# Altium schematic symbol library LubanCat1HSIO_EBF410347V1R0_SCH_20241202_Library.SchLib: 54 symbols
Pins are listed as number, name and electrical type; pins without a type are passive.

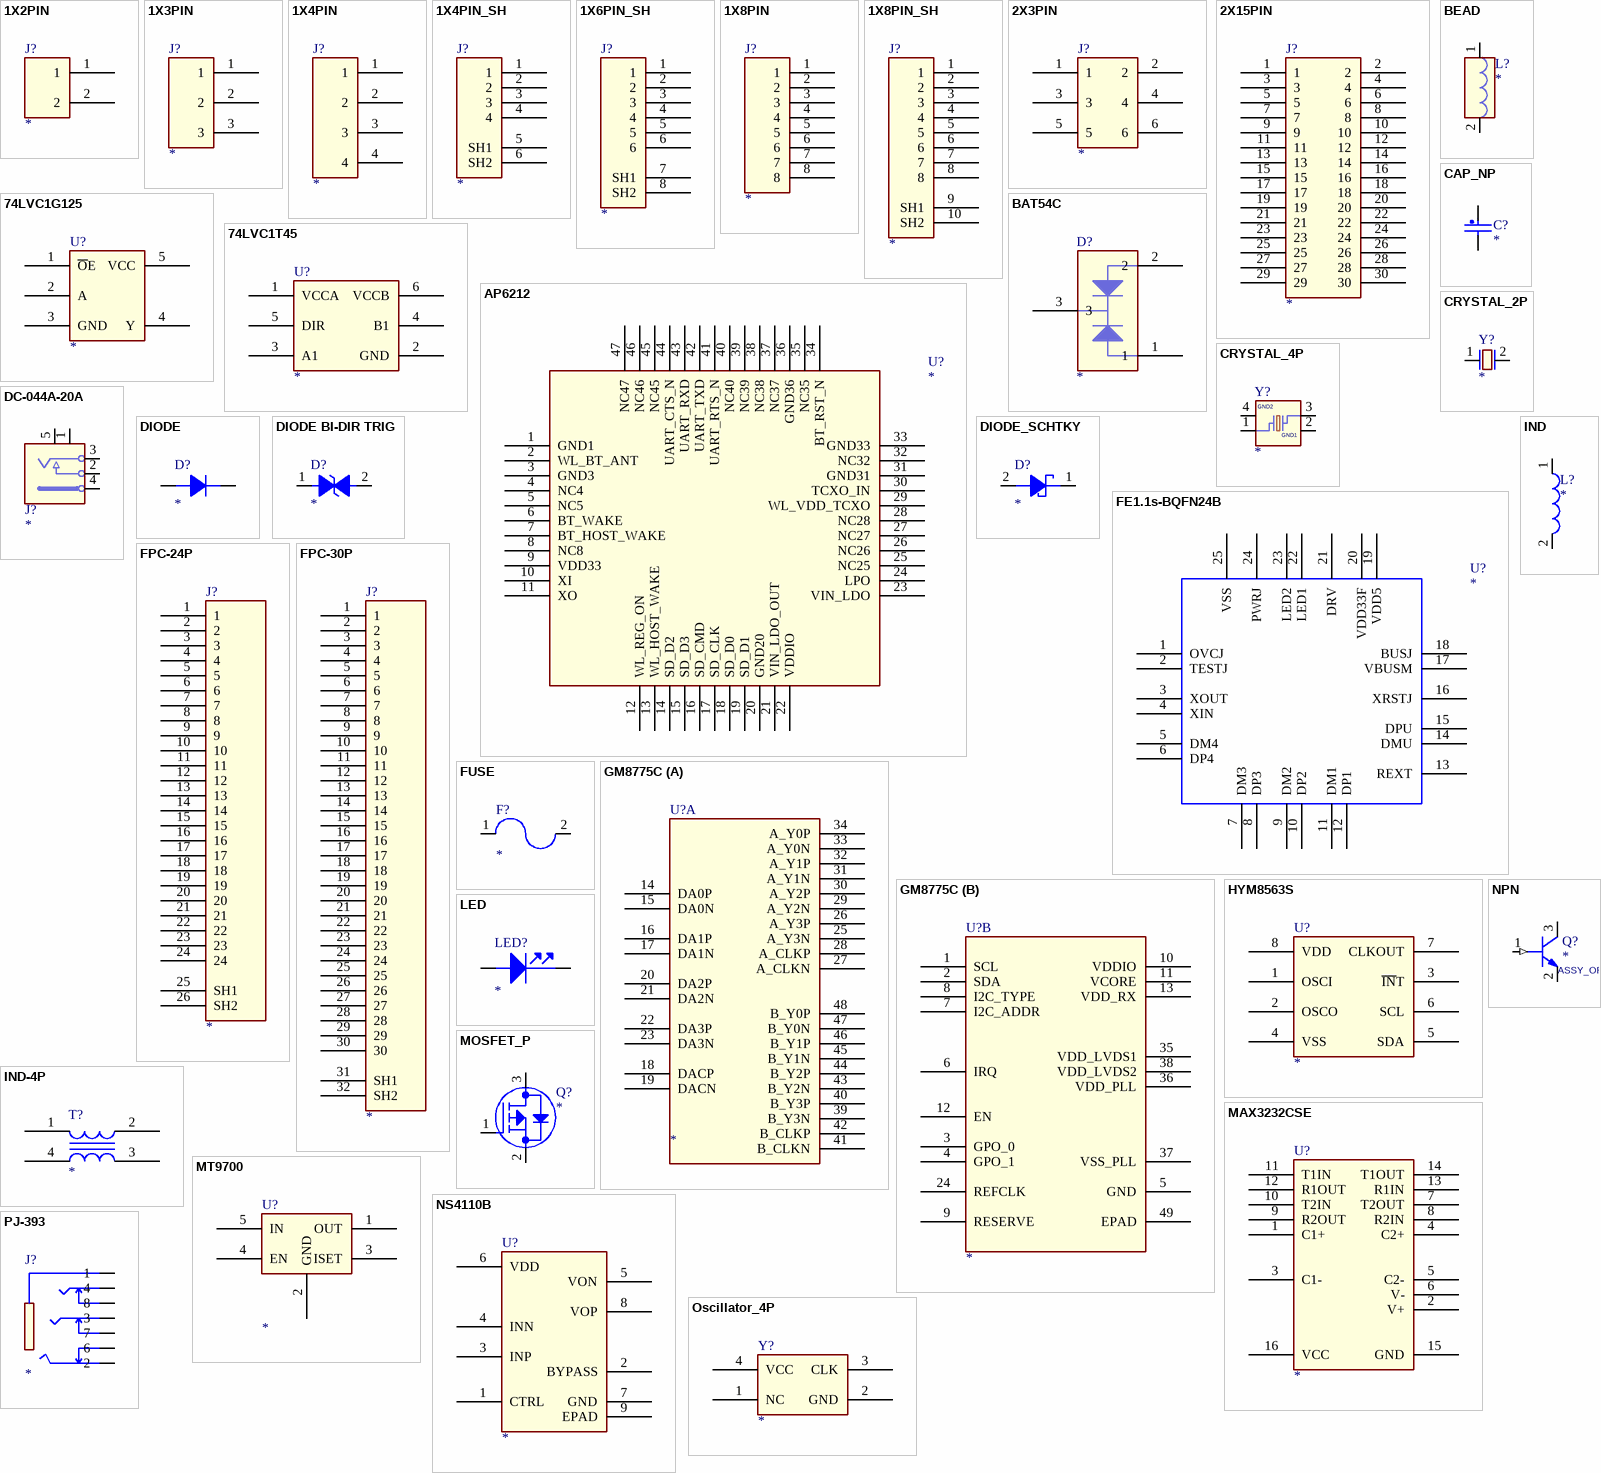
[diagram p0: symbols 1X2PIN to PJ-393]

## 1X2PIN
designator J?
pins: 1, 2

## 1X3PIN
designator J?
pins: 1, 2, 3

## 1X4PIN
designator J?
pins: 1, 2, 3, 4

## 1X4PIN_SH
designator J?
pins: 1, 2, 3, 4, 5 SH1, 6 SH2

## 1X6PIN_SH
designator J?
pins: 1, 2, 3, 4, 5, 6, 7 SH1, 8 SH2

## 1X8PIN
designator J?
pins: 1, 2, 3, 4, 5, 6, 7, 8

## 1X8PIN_SH
designator J?
pins: 1, 2, 3, 4, 5, 6, 7, 8, 9 SH1, 10 SH2

## 2X3PIN
designator J?
pins: 1, 2, 3, 4, 5, 6

## 2X15PIN
designator J?
pins: 1, 2, 3, 4, 5, 6, 7, 8, 9, 10, 11, 12, 13, 14, 15, 16, 17, 18, 19, 20, 21, 22, 23, 24, 25, 26, 27, 28, 29, 30

## 74LVC1G125
designator U?
footprint SOT-353
pins: 1 ~{O}E, 2 A, 3 GND, 4 Y, 5 VCC

## 74LVC1T45
designator U?
footprint SC70
pins: 1 VCCA, 2 GND, 3 A1, 4 B1, 5 DIR, 6 VCCB

## AP6212
designator U?
pins: 1 GND1, 2 WL_BT_ANT, 3 GND3, 4 NC4, 5 NC5, 6 BT_WAKE, 7 BT_HOST_WAKE, 8 NC8, 9 VDD33, 10 XI, 11 XO, 12 WL_REG_ON, 13 WL_HOST_WAKE, 14 SD_D2, 15 SD_D3, 16 SD_CMD, 17 SD_CLK, 18 SD_D0, 19 SD_D1, 20 GND20, 21 VIN_LDO_OUT, 22 VDDIO, 23 VIN_LDO, 24 LPO, 25 NC25, 26 NC26, 27 NC27, 28 NC28, 29 WL_VDD_TCXO, 30 TCXO_IN, 31 GND31, 32 NC32, 33 GND33, 34 BT_RST_N, 35 NC35, 36 GND36, 37 NC37, 38 NC38, 39 NC39, 40 NC40, 41 UART_RTS_N, 42 UART_TXD, 43 UART_RXD, 44 UART_CTS_N, 45 NC45, 46 NC46, 47 NC47

## BAT54C
designator D?
footprint SOT23
pins: 1, 2, 3

## BEAD
designator L?
CLASS: DISCRETE
pins: 1, 2

## CAP_NP
designator C?
CLASS: DISCRETE
pins: 1, 2

## CRYSTAL_2P
designator Y?
footprint 3215
pins: 1, 2

## CRYSTAL_4P
designator Y?
CLASS: IC
pins: 1, 2 GND1 (power), 3, 4 GND2 (power)

## DC-044A-20A
designator J?
footprint dc_in_th_3p_10r1x11r6
pins: 1, 2, 3, 4, 5

## DIODE
designator D?
pins: 1 K, 2 A

## DIODE BI-DIR TRIG
designator D?
footprint D0603/SMD
pins: 1, 2

## DIODE_SCHTKY
designator D?
CLASS: IC
pins: 1, 2

## FE1.1s-BQFN24B
designator U?
pins: 1 OVCJ, 2 TESTJ, 3 XOUT, 4 XIN, 5 DM4, 6 DP4, 7 DM3, 8 DP3, 9 DM2, 10 DP2, 11 DM1, 12 DP1, 13 REXT, 14 DMU, 15 DPU, 16 XRSTJ, 17 VBUSM, 18 BUSJ, 19 VDD5, 20 VDD33F, 21 DRV, 22 LED1, 23 LED2, 24 PWRJ, 25 VSS

## FPC-24P
designator J?
pins: 1, 2, 3, 4, 5, 6, 7, 8, 9, 10, 11, 12, 13, 14, 15, 16, 17, 18, 19, 20, 21, 22, 23, 24, 25 SH1, 26 SH2

## FPC-30P
designator J?
footprint FPC-30P-0P5
pins: 1, 2, 3, 4, 5, 6, 7, 8, 9, 10, 11, 12, 13, 14, 15, 16, 17, 18, 19, 20, 21, 22, 23, 24, 25, 26, 27, 28, 29, 30, 31 SH1, 32 SH2

## FUSE
designator F?
pins: 1, 2

## GM8775C
designator U?
part A pins: 14 DA0P, 15 DA0N, 16 DA1P, 17 DA1N, 18 DACP, 19 DACN, 20 DA2P, 21 DA2N, 22 DA3P, 23 DA3N, 25 A_Y3N, 26 A_Y3P, 27 A_CLKN, 28 A_CLKP, 29 A_Y2N, 30 A_Y2P, 31 A_Y1N, 32 A_Y1P, 33 A_Y0N, 34 A_Y0P, 39 B_Y3N, 40 B_Y3P, 41 B_CLKN, 42 B_CLKP, 43 B_Y2N, 44 B_Y2P, 45 B_Y1N, 46 B_Y1P, 47 B_Y0N, 48 B_Y0P
part B pins: 1 SCL, 2 SDA, 3 GPO_0, 4 GPO_1, 5 GND, 6 IRQ, 7 I2C_ADDR, 8 I2C_TYPE, 9 RESERVE, 10 VDDIO, 11 VCORE, 12 EN, 13 VDD_RX, 24 REFCLK, 35 VDD_LVDS1, 36 VDD_PLL, 37 VSS_PLL, 38 VDD_LVDS2, 49 EPAD

## HYM8563S
designator U?
pins: 1 OSCI, 2 OSCO, 3 ~{IN}T, 4 VSS, 5 SDA, 6 SCL, 7 CLKOUT, 8 VDD

## IND
designator L?
CLASS: DISCRETE
pins: 1, 2

## IND-4P
designator T?
pins: 1, 2, 3, 4

## LED
designator LED?
pins: 1 CATHODE, 2 ANODE

## MAX3232CSE
designator U?
footprint 16
pins: 1 C1+, 2 V+, 3 C1-, 4 C2+, 5 C2-, 6 V-, 7 T2OUT, 8 R2IN, 9 R2OUT, 10 T2IN, 11 T1IN, 12 R1OUT, 13 R1IN, 14 T1OUT, 15 GND (power), 16 VCC (power)

## MOSFET_P
designator Q?
CLASS: IC
pins: 1 GATE, 2 SOURCE, 3 DRAIN

## MT9700
designator U?
pins: 1 OUT, 2 GND, 3 ISET, 4 EN, 5 IN

## NPN
designator Q?
CLASS: IC
pins: 1 BASE (in), 2 EMITTER, 3 COLLECTOR

## NS4110B
designator U?
pins: 1 CTRL, 2 BYPASS, 3 INP, 4 INN, 5 VON, 6 VDD, 7 GND, 8 VOP, 9 EPAD

## Oscillator_4P
designator Y?
footprint 3225
pins: 1 NC, 2 GND, 3 CLK, 4 VCC

## PJ-393
designator J?
footprint audio_smd_7p_6r0x8r8
pins: 1, 2, 3, 4, 6, 7, 8

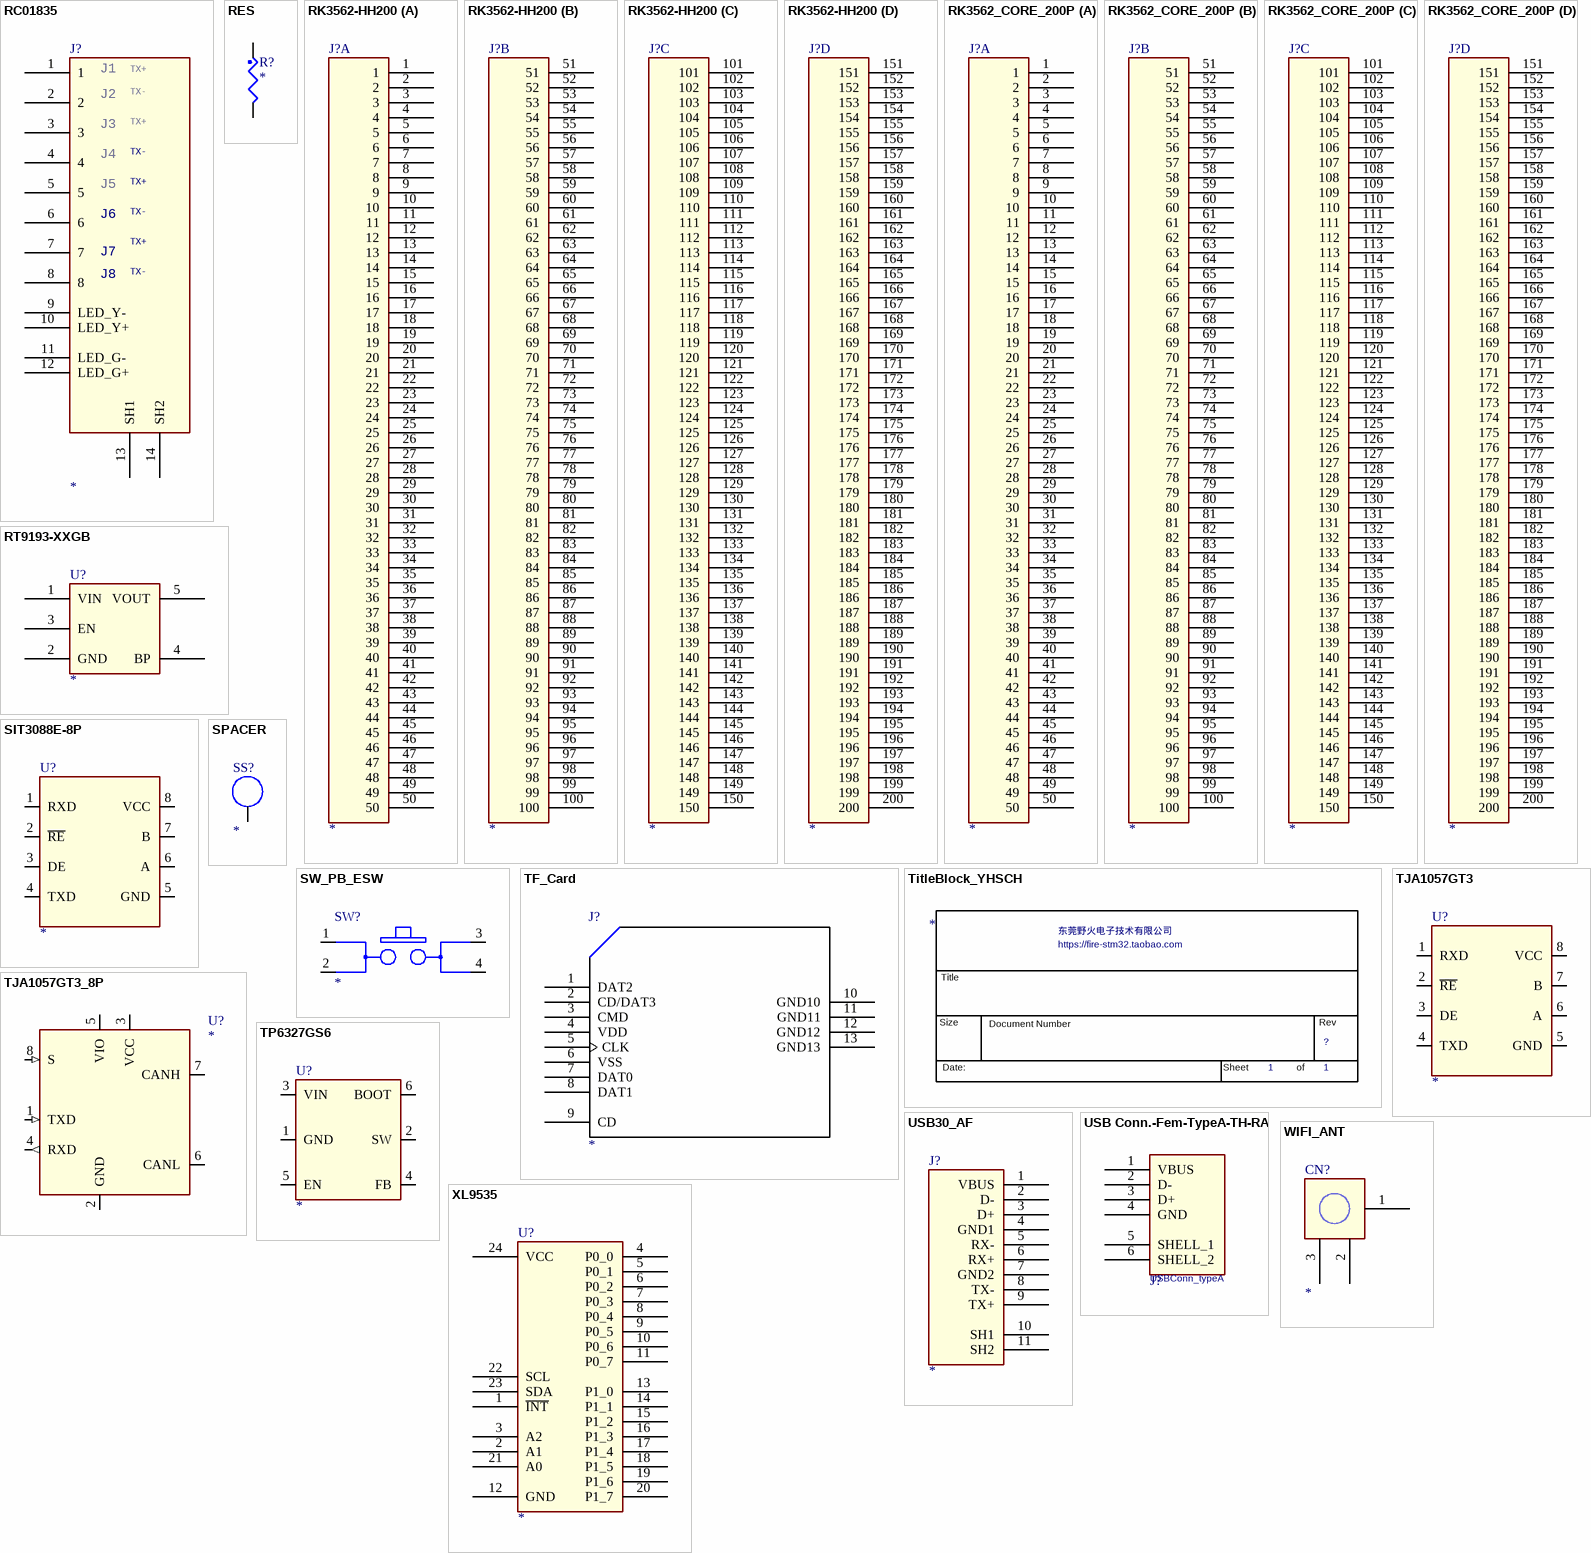
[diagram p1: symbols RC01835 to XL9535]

## RC01835
designator J?
pins: 1, 2, 3, 4, 5, 6, 7, 8, 9 LED_Y-, 10 LED_Y+, 11 LED_G-, 12 LED_G+, 13 SH1, 14 SH2

## RES
designator R?
CLASS: DISCRETE
pins: 1, 2

## RK3562-HH200
designator J?
part A pins: 1, 2, 3, 4, 5, 6, 7, 8, 9, 10, 11, 12, 13, 14, 15, 16, 17, 18, 19, 20, 21, 22, 23, 24, 25, 26, 27, 28, 29, 30, 31, 32, 33, 34, 35, 36, 37, 38, 39, 40, 41, 42, 43, 44, 45, 46, 47, 48, 49, 50
part B pins: 51, 52, 53, 54, 55, 56, 57, 58, 59, 60, 61, 62, 63, 64, 65, 66, 67, 68, 69, 70, 71, 72, 73, 74, 75, 76, 77, 78, 79, 80, 81, 82, 83, 84, 85, 86, 87, 88, 89, 90, 91, 92, 93, 94, 95, 96, 97, 98, 99, 100
part C pins: 101, 102, 103, 104, 105, 106, 107, 108, 109, 110, 111, 112, 113, 114, 115, 116, 117, 118, 119, 120, 121, 122, 123, 124, 125, 126, 127, 128, 129, 130, 131, 132, 133, 134, 135, 136, 137, 138, 139, 140, 141, 142, 143, 144, 145, 146, 147, 148, 149, 150
part D pins: 151, 152, 153, 154, 155, 156, 157, 158, 159, 160, 161, 162, 163, 164, 165, 166, 167, 168, 169, 170, 171, 172, 173, 174, 175, 176, 177, 178, 179, 180, 181, 182, 183, 184, 185, 186, 187, 188, 189, 190, 191, 192, 193, 194, 195, 196, 197, 198, 199, 200

## RK3562_CORE_200P
designator J?
part A pins: 1, 2, 3, 4, 5, 6, 7, 8, 9, 10, 11, 12, 13, 14, 15, 16, 17, 18, 19, 20, 21, 22, 23, 24, 25, 26, 27, 28, 29, 30, 31, 32, 33, 34, 35, 36, 37, 38, 39, 40, 41, 42, 43, 44, 45, 46, 47, 48, 49, 50
part B pins: 51, 52, 53, 54, 55, 56, 57, 58, 59, 60, 61, 62, 63, 64, 65, 66, 67, 68, 69, 70, 71, 72, 73, 74, 75, 76, 77, 78, 79, 80, 81, 82, 83, 84, 85, 86, 87, 88, 89, 90, 91, 92, 93, 94, 95, 96, 97, 98, 99, 100
part C pins: 101, 102, 103, 104, 105, 106, 107, 108, 109, 110, 111, 112, 113, 114, 115, 116, 117, 118, 119, 120, 121, 122, 123, 124, 125, 126, 127, 128, 129, 130, 131, 132, 133, 134, 135, 136, 137, 138, 139, 140, 141, 142, 143, 144, 145, 146, 147, 148, 149, 150
part D pins: 151, 152, 153, 154, 155, 156, 157, 158, 159, 160, 161, 162, 163, 164, 165, 166, 167, 168, 169, 170, 171, 172, 173, 174, 175, 176, 177, 178, 179, 180, 181, 182, 183, 184, 185, 186, 187, 188, 189, 190, 191, 192, 193, 194, 195, 196, 197, 198, 199, 200

## RT9193-XXGB
designator U?
pins: 1 VIN, 2 GND, 3 EN, 4 BP, 5 VOUT

## SIT3088E-8P
designator U?
CLASS: IC
pins: 1 RXD, 2 ~{RE}, 3 DE, 4 TXD, 5 GND, 6 A, 7 B, 8 VCC

## SPACER
designator SS?
CLASS: IC
pins: 1 NC_1

## SW_PB_ESW
designator SW?
CLASS: IC
pins: 1 A1, 2 A2, 3 B1, 4 B2

## TF_Card
designator J?
CLASS: IO
pins: 1 DAT2, 2 CD/DAT3, 3 CMD, 4 VDD (power), 5 CLK, 6 VSS (power), 7 DAT0, 8 DAT1, 9 CD, 10 GND10, 11 GND11, 12 GND12, 13 GND13

## TitleBlock_YHSCH
designator *  Page Count: 1  OrgName: 东莞野火电子技术有限公司  (graphical)

## TJA1057GT3
designator U?
CLASS: IC
pins: 1 RXD, 2 ~{RE}, 3 DE, 4 TXD, 5 GND, 6 A, 7 B, 8 VCC

## TJA1057GT3_8P
designator U?
CLASS: IC
pins: 1 TXD (in), 2 GND (power), 3 VCC (power), 4 RXD (out), 5 VIO (power), 6 CANL (io), 7 CANH (io), 8 S (in)

## TP6327GS6
designator U?
pins: 1 GND, 2 SW, 3 VIN, 4 FB, 5 EN, 6 BOOT

## USB30_AF
designator J?
pins: 1 VBUS, 2 D-, 3 D+, 4 GND1, 5 RX-, 6 RX+, 7 GND2, 8 TX-, 9 TX+, 10 SH1, 11 SH2

## USB Conn.-Fem-TypeA-TH-RA
designator J?, comment USBConn_typeA
P/N: 180K00400S
pins: 1 VBUS, 2 D-, 3 D+, 4 GND, 5 SHELL_1, 6 SHELL_2

## WIFI_ANT
designator CN?
footprint UFL-3
pins: 1, 2, 3

## XL9535
designator U?
pins: 1 ~{INT}, 2 A1, 3 A2, 4 P0_0, 5 P0_1, 6 P0_2, 7 P0_3, 8 P0_4, 9 P0_5, 10 P0_6, 11 P0_7, 12 GND, 13 P1_0, 14 P1_1, 15 P1_2, 16 P1_3, 17 P1_4, 18 P1_5, 19 P1_6, 20 P1_7, 21 A0, 22 SCL, 23 SDA, 24 VCC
